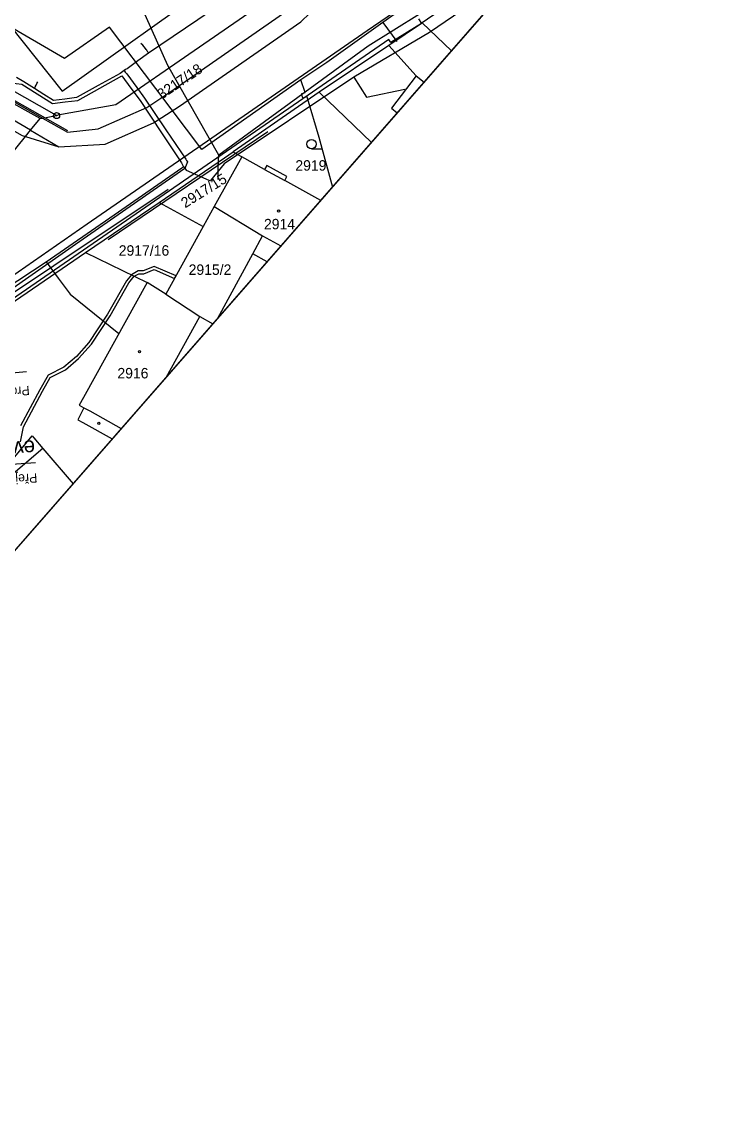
# Model space of a CAD drawing. Extents: x -620475 to -619963, y -1123010 to -1122510.
# Drawn here: x -620075.4 to -619962.9, y -1123010.1 to -1122830.6 of the extents above; entities that cross this region are included whole.
import ezdxf

# ---------------------------------------------------------------- set-up
doc = ezdxf.new("R2010")
doc.units = 0
for name, color, linetype in [('CETIN', 7, 'Continuous'), ('GasNet', 7, 'Continuous'), ('Hranice parcel', 7, 'Continuous'), ('Město Bystřice-osvětlení', 7, 'Continuous'), ('Parcelní čísla', 7, 'Continuous'), ('Rámečky', 7, 'Continuous'), ('Rámečky-tisk', 7, 'Continuous'), ('VAS stoka', 7, 'Continuous'), ('VAS vodovod', 7, 'Continuous'), ('Vnitřní kresba', 7, 'Continuous'), ('Vrstva 19', 7, 'Continuous'), ('Vrstva 4', 7, 'Continuous'), ('Věcná břemena k části', 7, 'Continuous'), ('Značky bodu BP', 7, 'Continuous'), ('Značky budov', 7, 'Continuous'), ('Značky kultur', 7, 'Continuous')]:
    doc.layers.add(name, color=color, linetype=linetype)

msp = doc.modelspace()

# ---------------------------------------------------------------- linework, layer by layer
at = {"layer": 'CETIN'}
for points in [[(-620322.39, -1122622.26), (-620301.06, -1122636.75), (-620273.54, -1122652.22), (-620253.25, -1122663.16), (-620204.02, -1122698.84), (-620159.64, -1122769.19), (-620144.67, -1122791.29), (-620140.33, -1122798.33), (-620134.98, -1122805.25), (-620121.23, -1122817.18), (-620095.95, -1122832.42), (-620068, -1122848.18)], [(-620127.25, -1122919.48), (-620126.15, -1122907.43), (-620051.64, -1122857.73)]]:
    msp.add_lwpolyline(points, dxfattribs=at)
at = {"layer": 'GasNet'}
for points in [[(-620046.14, -1122851.29), (-620053.62, -1122841.38), (-620061.16, -1122831.41), (-620068.48, -1122836.5), (-620088.2, -1122824.99), (-620093.66, -1122821.84), (-620093.89, -1122821.71), (-620111.26, -1122811.68), (-620133.38, -1122798.37), (-620145.72, -1122781.6), (-620162.54, -1122758.52), (-620166.3, -1122761.04), (-620166.89, -1122761.43), (-620167.47, -1122761.82), (-620169.13, -1122762.93), (-620169.19, -1122762.97)], [(-619978.45, -1122804.33), (-619997.91, -1122817.46), (-620001.69, -1122820.05), (-620016.67, -1122830.62), (-620025.79, -1122837.14), (-620030.05, -1122839.94), (-620046.14, -1122851.29)], [(-620016.67, -1122830.62), (-620014.42, -1122833.73)], [(-620029.59, -1122842.13), (-620029.3, -1122842.03), (-620030.05, -1122839.94)], [(-620029.59, -1122842.13), (-620029.96, -1122842.27), (-620029.73, -1122842.93), (-620029.07, -1122842.69), (-620029, -1122842.88), (-620027.09, -1122849.31), (-620024.89, -1122857.41)]]:
    msp.add_lwpolyline(points, dxfattribs=at)
at = {"layer": 'Hranice parcel'}
for p, q in [((-620010.26, -1122830.7), (-620005.5, -1122835.25)), ((-620015.7, -1122834.36), (-620027.05, -1122841.96)), ((-620027.05, -1122841.96), (-620041.07, -1122851.68)), ((-620027.05, -1122841.96), (-620018.53, -1122850.14)), ((-620074.02, -1122848.16), (-620072.47, -1122846.25)), ((-620039.65, -1122852.48), (-620044.13, -1122860.59)), ((-620041.07, -1122851.68), (-620039.65, -1122852.48)), ((-620065.08, -1122868.06), (-620053.1, -1122859.89)), ((-620053.1, -1122859.89), (-620045.93, -1122863.84)), ((-620044.13, -1122860.59), (-620045.93, -1122863.84)), ((-620044.13, -1122860.59), (-620036.26, -1122865.31)), ((-620045.93, -1122863.84), (-620052.01, -1122874.84)), ((-620037.86, -1122868.27), (-620036.26, -1122865.31)), ((-620036.26, -1122865.31), (-620033.26, -1122866.98)), ((-620081.71, -1122879.39), (-620065.08, -1122868.06)), ((-620065.08, -1122868.06), (-620055.03, -1122872.95)), ((-620043.52, -1122878.71), (-620037.86, -1122868.27)), ((-620035.52, -1122869.56), (-620037.86, -1122868.27)), ((-620052.01, -1122874.84), (-620055.03, -1122872.95)), ((-620052.01, -1122874.84), (-620046.45, -1122878.47)), ((-620046.45, -1122878.47), (-620044.34, -1122879.65)), ((-620072.03, -1122899.92), (-620067.11, -1122905.68))]:
    msp.add_line(p, q, dxfattribs=at)
for points in [[(-620072.47, -1122846.25), (-620119.48, -1122820.03), (-620130.17, -1122810.08), (-620136, -1122804.68), (-620136.79, -1122803.52), (-620163.81, -1122763.48)], [(-620069.79, -1122845.77), (-620093.24, -1122832.45), (-620114.36, -1122820.1), (-620123.37, -1122813.77), (-620129.15, -1122808.98), (-620134.98, -1122803.58), (-620147.22, -1122786.5), (-620163.81, -1122763.48)], [(-620074.02, -1122848.16), (-620095.17, -1122835.78), (-620116.57, -1122823.25), (-620125.58, -1122816.92), (-620133.3, -1122810.53), (-620139.43, -1122803.84), (-620150.35, -1122788.75), (-620165.02, -1122768.39), (-620166.09, -1122767.67), (-620166.7, -1122767.69)], [(-619977.35, -1122803.07), (-619989.26, -1122811.36), (-619995.85, -1122815.89), (-620011.68, -1122826.8), (-620019.22, -1122832.01), (-620044.54, -1122849.47), (-620064.79, -1122863.44), (-620079.86, -1122873.87), (-620081.95, -1122879.05), (-620081.71, -1122879.39)], [(-620074.02, -1122848.16), (-620069.41, -1122850.86), (-620061.9, -1122850.43), (-620053.99, -1122846.97), (-620049.77, -1122844.23), (-620030.04, -1122830.5), (-620028.57, -1122829.11), (-620027.57, -1122827.35), (-620023.65, -1122820.37), (-620022.03, -1122817.87), (-620021.18, -1122817.07)], [(-619988.22, -1122815.49), (-619988.48, -1122815.67), (-619991.93, -1122818.06), (-620010.26, -1122830.7)], [(-620026.52, -1122820.79), (-620038.5, -1122829.12), (-620047.37, -1122835.25), (-620060.13, -1122844.05), (-620068.97, -1122845.62), (-620069.79, -1122845.77)], [(-620079.53, -1122828.52), (-620068.86, -1122841.8), (-620043.43, -1122823.66)], [(-620010.26, -1122830.7), (-620010.39, -1122830.79), (-620015.7, -1122834.36)], [(-620015.7, -1122834.36), (-620011.24, -1122839.29), (-620015.25, -1122844.59), (-620014.33, -1122845.34)], [(-620072.47, -1122846.25), (-620072.09, -1122846.18), (-620069.79, -1122845.77)], [(-620080.86, -1122856.55), (-620079.9, -1122855.37), (-620074.83, -1122849.15), (-620074.02, -1122848.16)], [(-620053.1, -1122859.89), (-620042.46, -1122852.64), (-620041.07, -1122851.68)], [(-620026.8, -1122859.59), (-620032.66, -1122856.34), (-620032.3, -1122855.67), (-620035.58, -1122853.89), (-620035.95, -1122854.57), (-620039.65, -1122852.48)], [(-620055.03, -1122872.95), (-620065.41, -1122891.61), (-620066.12, -1122892.87), (-620065.34, -1122893.31), (-620066.33, -1122895.25), (-620065.54, -1122895.69), (-620060.72, -1122898.37)], [(-620051.96, -1122888.36), (-620046.45, -1122878.47)], [(-620092.29, -1122886.6), (-620081.3, -1122906.94), (-620073.77, -1122897.87), (-620073.48, -1122898.22), (-620072.03, -1122899.92)], [(-620072.03, -1122899.92), (-620081.39, -1122907.9), (-620081.76, -1122907.52)]]:
    msp.add_lwpolyline(points, dxfattribs=at)
at = {"layer": 'Město Bystřice-osvětlení'}
msp.add_line((-620061.39, -1122865.95), (-620035.38, -1122848.34), dxfattribs=at)
at = {"layer": 'Rámečky'}
msp.add_line((-620158.49, -1123010.14), (-619962.95, -1122786.6), dxfattribs=at)
at = {"layer": 'Rámečky-tisk'}
msp.add_lwpolyline([(-620158.49, -1123010.14), (-619962.95, -1122786.6), (-620279.07, -1122510.07)], dxfattribs=at)
at = {"layer": 'VAS stoka'}
for p, q in [((-620019.05, -1122834.47), (-620043.37, -1122852.23)), ((-620043.37, -1122852.23), (-620051.68, -1122837.63))]:
    msp.add_line(p, q, dxfattribs=at)
for points in [[(-620051.68, -1122837.63), (-620057.91, -1122823.65), (-620061.86, -1122814.79)], [(-619997.17, -1122820.75), (-619998.31, -1122821.46), (-620010.73, -1122829.25), (-620019.05, -1122834.47)], [(-620043.48, -1122856.17), (-620043.46, -1122854.13), (-620043.37, -1122852.23)]]:
    msp.add_lwpolyline(points, dxfattribs=at)
at = {"layer": 'VAS vodovod'}
for p, q in [((-620019.35, -1122842.75), (-620013.1, -1122841.47)), ((-620067.58, -1122874.84), (-620059.66, -1122881.25))]:
    msp.add_line(p, q, dxfattribs=at)
for points in [[(-619974.71, -1122776.31), (-619980.2, -1122780.38), (-619982.02, -1122781.49), (-619983.73, -1122782.53), (-619988.19, -1122785.41), (-619992.55, -1122788.24), (-619997.47, -1122791.49), (-620002.4, -1122794.74), (-620006.71, -1122797.84), (-620011.04, -1122800.95), (-620011.83, -1122801.49), (-620012.62, -1122802.02), (-620013.19, -1122804.65), (-620013.77, -1122807.28), (-620018.79, -1122810.81), (-620023.82, -1122814.35), (-620035.32, -1122822.27), (-620046.82, -1122830.19), (-620050.81, -1122832.92), (-620054.81, -1122835.64), (-620056.56, -1122836.89), (-620058.31, -1122838.14), (-620058.56, -1122838.3), (-620058.81, -1122838.46)], [(-619993.63, -1122821.67), (-620009.07, -1122832.23), (-620021.42, -1122839.54), (-620042.52, -1122853.63), (-620044.71, -1122856.33)], [(-620094.32, -1122826.78), (-620093.93, -1122828.82), (-620093.38, -1122831.42), (-620088.09, -1122834.26), (-620082.79, -1122837.11), (-620081.87, -1122837.67), (-620081.6, -1122837.83), (-620080.01, -1122838.8), (-620077.23, -1122840.48), (-620076.35, -1122840.57), (-620075.46, -1122840.67), (-620072.96, -1122842.22), (-620070.45, -1122843.78), (-620068.4, -1122843.54), (-620066.34, -1122843.3), (-620062.75, -1122841.31), (-620059.16, -1122839.32), (-620057.68, -1122841.33), (-620056.2, -1122843.34), (-620052.72, -1122848.56), (-620049.46, -1122853.44), (-620049.29, -1122853.76), (-620049.11, -1122854.09)], [(-620054.81, -1122835.64), (-620054.88, -1122835.52), (-620054.95, -1122835.4), (-620055.02, -1122835.27), (-620055.09, -1122835.14), (-620055.19, -1122835), (-620055.29, -1122834.87), (-620055.52, -1122834.59), (-620055.75, -1122834.32), (-620056.05, -1122834.04)], [(-620058.81, -1122838.46), (-620058.6, -1122838.7), (-620058.39, -1122838.94), (-620058.35, -1122838.97), (-620056.75, -1122841.18), (-620055.49, -1122842.93), (-620052.02, -1122848.07), (-620048.77, -1122852.88), (-620048.64, -1122853.08), (-620048.5, -1122853.27), (-620048.71, -1122853.82), (-620048.92, -1122854.36), (-620066.7, -1122866.75), (-620084.48, -1122879.15)], [(-620058.81, -1122838.46), (-620059.44, -1122838.9), (-620063.01, -1122840.88), (-620066.44, -1122842.78), (-620066.57, -1122842.85), (-620068.43, -1122843.09), (-620070.28, -1122843.33), (-620071.85, -1122842.34), (-620073.41, -1122841.36), (-620075.13, -1122840.28), (-620076.29, -1122839.55)], [(-620073.41, -1122841.36), (-620073.27, -1122841.11), (-620073.12, -1122840.84), (-620073.12, -1122840.84), (-620072.99, -1122840.57), (-620072.86, -1122840.3)], [(-620021.42, -1122839.54), (-620020.38, -1122841.14), (-620019.35, -1122842.75)], [(-620142.98, -1122992.41), (-620138.82, -1122978.35), (-620134.02, -1122962.12), (-620127.91, -1122941.45), (-620121.79, -1122920.78), (-620120.52, -1122917.15), (-620119.24, -1122913.52), (-620115.38, -1122909), (-620111.52, -1122904.47), (-620108.12, -1122900.4), (-620104.72, -1122896.32), (-620104.31, -1122896.03), (-620103.9, -1122895.74), (-620097.91, -1122891.45), (-620091.91, -1122887.16), (-620088.52, -1122882.87), (-620085.12, -1122878.57), (-620078.3, -1122874.06), (-620071.49, -1122869.56), (-620071.48, -1122869.55), (-620060.44, -1122861.92), (-620049.39, -1122854.28), (-620049.25, -1122854.18), (-620049.11, -1122854.08)], [(-620049.11, -1122854.09), (-620049.1, -1122854.1), (-620048.93, -1122854.34), (-620048.82, -1122854.48), (-620048.81, -1122854.51), (-620048.68, -1122854.67), (-620046.84, -1122855.48), (-620044.99, -1122856.3), (-620044.85, -1122856.32), (-620044.71, -1122856.33)], [(-620071.48, -1122869.55), (-620069.53, -1122872.21), (-620067.58, -1122874.84)]]:
    msp.add_lwpolyline(points, dxfattribs=at)
at = {"layer": 'Vnitřní kresba'}
for p, q in [((-620127.92, -1122819.29), (-620075.39, -1122849.03)), ((-620051.34, -1122841.97), (-620031.61, -1122828.24)), ((-620010.39, -1122830.79), (-620015.39, -1122833.86)), ((-620010.9, -1122830.03), (-620010.39, -1122830.79)), ((-620015.73, -1122833.37), (-620081.95, -1122879.05)), ((-620015.39, -1122833.86), (-620015.73, -1122833.37)), ((-620072.09, -1122846.18), (-620093.98, -1122833.75)), ((-620011.24, -1122839.29), (-620009.96, -1122840.34)), ((-620055.09, -1122844.45), (-620051.34, -1122841.97)), ((-620063, -1122847.91), (-620055.09, -1122844.45)), ((-620072.09, -1122846.18), (-620068.02, -1122848.49)), ((-620075.39, -1122849.03), (-620074.83, -1122849.15)), ((-620074.83, -1122849.15), (-620069.41, -1122850.86)), ((-620068.02, -1122848.49), (-620063, -1122847.91)), ((-620035.95, -1122854.57), (-620032.66, -1122856.34)), ((-620065.34, -1122893.31), (-620064.4, -1122893.83)), ((-620064.4, -1122893.83), (-620059.25, -1122896.69))]:
    msp.add_line(p, q, dxfattribs=at)
at = {"layer": 'Vrstva 19'}
msp.add_line((-620074.7, -1122887.47), (-620134.45, -1122892.95), dxfattribs=at)
at = {"layer": 'Vrstva 4'}
msp.add_line((-620133.06, -1122906.27), (-620073.2, -1122902.2), dxfattribs=at)
at = {"layer": 'Věcná břemena k části'}
msp.add_lwpolyline([(-620075.64, -1122898.87), (-620075.16, -1122896.43), (-620072.09, -1122890.61), (-620070.81, -1122888.41), (-620068.34, -1122887.13), (-620066.22, -1122885.31), (-620064.12, -1122882.97), (-620061.08, -1122878.34), (-620058.01, -1122872.96), (-620057.14, -1122871.92), (-620056.39, -1122871.51), (-620055.57, -1122871.52), (-620053.9, -1122870.84), (-620050.59, -1122872.27), (-620050.35, -1122871.83), (-620053.9, -1122870.3), (-620055.67, -1122871.02), (-620056.51, -1122871.01), (-620057.61, -1122871.7), (-620058.43, -1122872.68), (-620061.5, -1122878.08), (-620064.52, -1122882.67), (-620066.57, -1122884.95), (-620068.62, -1122886.71), (-620071.17, -1122888.03), (-620072.53, -1122890.37), (-620075.64, -1122896.27)], dxfattribs=at)
at = {"layer": 'Značky bodu BP'}
for radius in [0.5, 0.0303]:
    msp.add_circle((-620069.79, -1122845.77), radius, dxfattribs=at)
at = {"layer": 'Značky budov'}
for centre in [(-620033.64, -1122861.3), (-620056.29, -1122884.18), (-620062.9, -1122895.84)]:
    msp.add_circle(centre, 0.175, dxfattribs=at)
at = {"layer": 'Značky kultur'}
msp.add_line((-620028.3, -1122851.16), (-620026.55, -1122851.16), dxfattribs=at)
msp.add_circle((-620028.3, -1122850.41), 0.75, dxfattribs=at)

# ---------------------------------------------------------------- texts
at = {"layer": 'Parcelní čísla'}
for s, rotation, p in [('3217/18', 34, (-620052.68, -1122843.2)), ('2917/15', 32, (-620048.86, -1122860.88))]:
    msp.add_text(s, height=1.7, rotation=rotation, dxfattribs=at).set_placement(p)
for s, p in [('2919', (-620030.92, -1122854.73)), ('2914', (-620036.03, -1122864.28)), ('2917/16', (-620059.67, -1122868.57)), ('2915/2', (-620048.29, -1122871.69)), ('2916', (-620059.89, -1122888.53))]:
    msp.add_text(s, height=1.7, dxfattribs=at).set_placement(p)
at = {"layer": 'Vrstva 19'}
msp.add_text('Propustek 17851', height=1.5, rotation=184.98, dxfattribs=at).set_placement((-620074.24, -1122889.72))
at = {"layer": 'Vrstva 4'}
for s, height, p in [('evid. km 63,686', 2.5, (-620073.37, -1122898.56)), ('Přejezd 7264', 1.5, (-620072.98, -1122903.95))]:
    msp.add_text(s, height=height, rotation=183.8855, dxfattribs=at).set_placement(p)

doc.saveas('drawing.dxf')
